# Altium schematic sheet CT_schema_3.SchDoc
size 306 x 215 mm
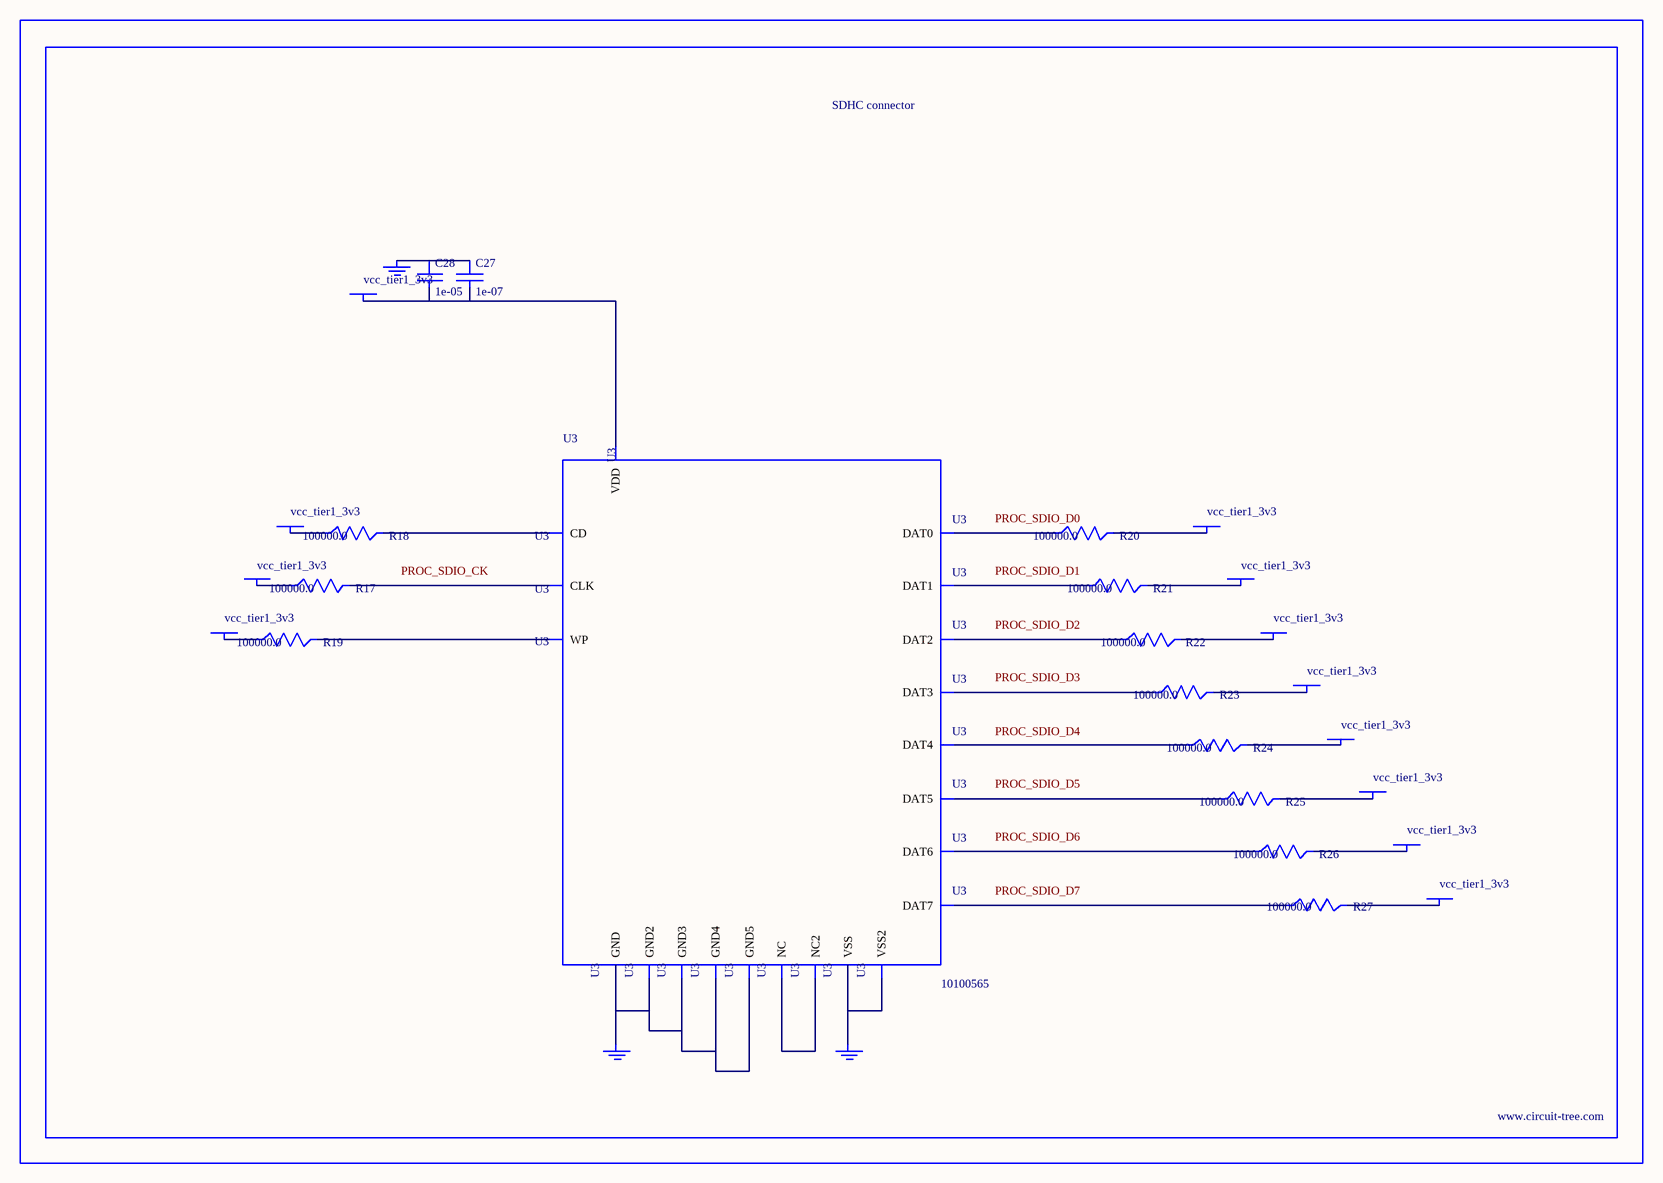
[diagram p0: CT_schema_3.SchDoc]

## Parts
BORDER2  (no value)
C27  1e-07  [C0402]
C28  1e-05  [C0805]
GND_INSTANCE_2_0  (no value)
GND_INSTANCE_2_1  (no value)
GND_INSTANCE_2_2  (no value)
POWER_INSTANCE_2_0  vcc_tier1_3v3
POWER_INSTANCE_2_1  vcc_tier1_3v3
POWER_INSTANCE_2_2  vcc_tier1_3v3
POWER_INSTANCE_2_3  vcc_tier1_3v3
POWER_INSTANCE_2_4  vcc_tier1_3v3
POWER_INSTANCE_2_5  vcc_tier1_3v3
POWER_INSTANCE_2_6  vcc_tier1_3v3
POWER_INSTANCE_2_7  vcc_tier1_3v3
POWER_INSTANCE_2_8  vcc_tier1_3v3
POWER_INSTANCE_2_9  vcc_tier1_3v3
POWER_INSTANCE_2_10  vcc_tier1_3v3
POWER_INSTANCE_2_11  vcc_tier1_3v3
R17  100000.0  [R0603]
R18  100000.0  [R0603]
R19  100000.0  [R0603]
R20  100000.0  [R0603]
R21  100000.0  [R0603]
R22  100000.0  [R0603]
R23  100000.0  [R0603]
R24  100000.0  [R0603]
R25  100000.0  [R0603]
R26  100000.0  [R0603]
R27  100000.0  [R0603]
U3  10100565  [10100565]

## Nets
NetC27_1: C27.1 C28.1 GND_INSTANCE_2_0.0(GND)
NetC27_2: C27.2 C28.2 POWER_INSTANCE_2_7.0(PWR) U3.9(VDD)
NetGND_INSTANCE_2_1_0: GND_INSTANCE_2_1.0(GND) U3.6(VSS) U3.10(VSS2)
NetGND_INSTANCE_2_2_0: GND_INSTANCE_2_2.0(GND) U3.12(GND) U3.16(GND2) U3.17(GND3) U3.20(GND4) U3.21(GND5)
NetPOWER_INSTANCE_2_0_0: POWER_INSTANCE_2_0.0(PWR) R19.1
NetPOWER_INSTANCE_2_1_0: POWER_INSTANCE_2_1.0(PWR) R18.1
NetPOWER_INSTANCE_2_2_0: POWER_INSTANCE_2_2.0(PWR) R21.2
NetPOWER_INSTANCE_2_3_0: POWER_INSTANCE_2_3.0(PWR) R20.2
NetPOWER_INSTANCE_2_4_0: POWER_INSTANCE_2_4.0(PWR) R27.2
NetPOWER_INSTANCE_2_5_0: POWER_INSTANCE_2_5.0(PWR) R26.2
NetPOWER_INSTANCE_2_6_0: POWER_INSTANCE_2_6.0(PWR) R17.1
NetPOWER_INSTANCE_2_8_0: POWER_INSTANCE_2_8.0(PWR) R25.2
NetPOWER_INSTANCE_2_9_0: POWER_INSTANCE_2_9.0(PWR) R24.2
NetPOWER_INSTANCE_2_10_0: POWER_INSTANCE_2_10.0(PWR) R23.2
NetPOWER_INSTANCE_2_11_0: POWER_INSTANCE_2_11.0(PWR) R22.2
NetR17_2: R17.2 U3.8(CLK)
NetR18_2: R18.2 U3.2(CD)
NetR19_2: R19.2 U3.1(WP)
NetR20_1: R20.1 U3.4(DAT0)
NetR21_1: R21.1 U3.3(DAT1)
NetR22_1: R22.1 U3.15(DAT2)
NetR23_1: R23.1 U3.14(DAT3)
NetR24_1: R24.1 U3.13(DAT4)
NetR25_1: R25.1 U3.11(DAT5)
NetR26_1: R26.1 U3.7(DAT6)
NetR27_1: R27.1 U3.5(DAT7)
NetU3_18: U3.18(NC) U3.19(NC2)

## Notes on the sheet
- Labels drawn without touching a wire or pin: PROC_SDIO_CK, PROC_SDIO_D0, PROC_SDIO_D1, PROC_SDIO_D2, PROC_SDIO_D3, PROC_SDIO_D4, PROC_SDIO_D5, PROC_SDIO_D6, PROC_SDIO_D7

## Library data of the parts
BORDER2 = BORDER_PAGE2
C27 = C0402C104K3RACTU
C28 = C0805C106K8RACTU
GND_INSTANCE_2_0-GND_INSTANCE_2_2 = GND
POWER_INSTANCE_2_0-POWER_INSTANCE_2_11 = PWR
R17-R27 = RC0603JR-07100KL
